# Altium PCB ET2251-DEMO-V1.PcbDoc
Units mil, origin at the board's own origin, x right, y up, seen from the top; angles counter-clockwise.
Board outline 5039.37 x 4724.41 mil, 2 copper layers (Top Layer, Bottom Layer); 99 components, 49 nets, 309 pads, 342 vias.
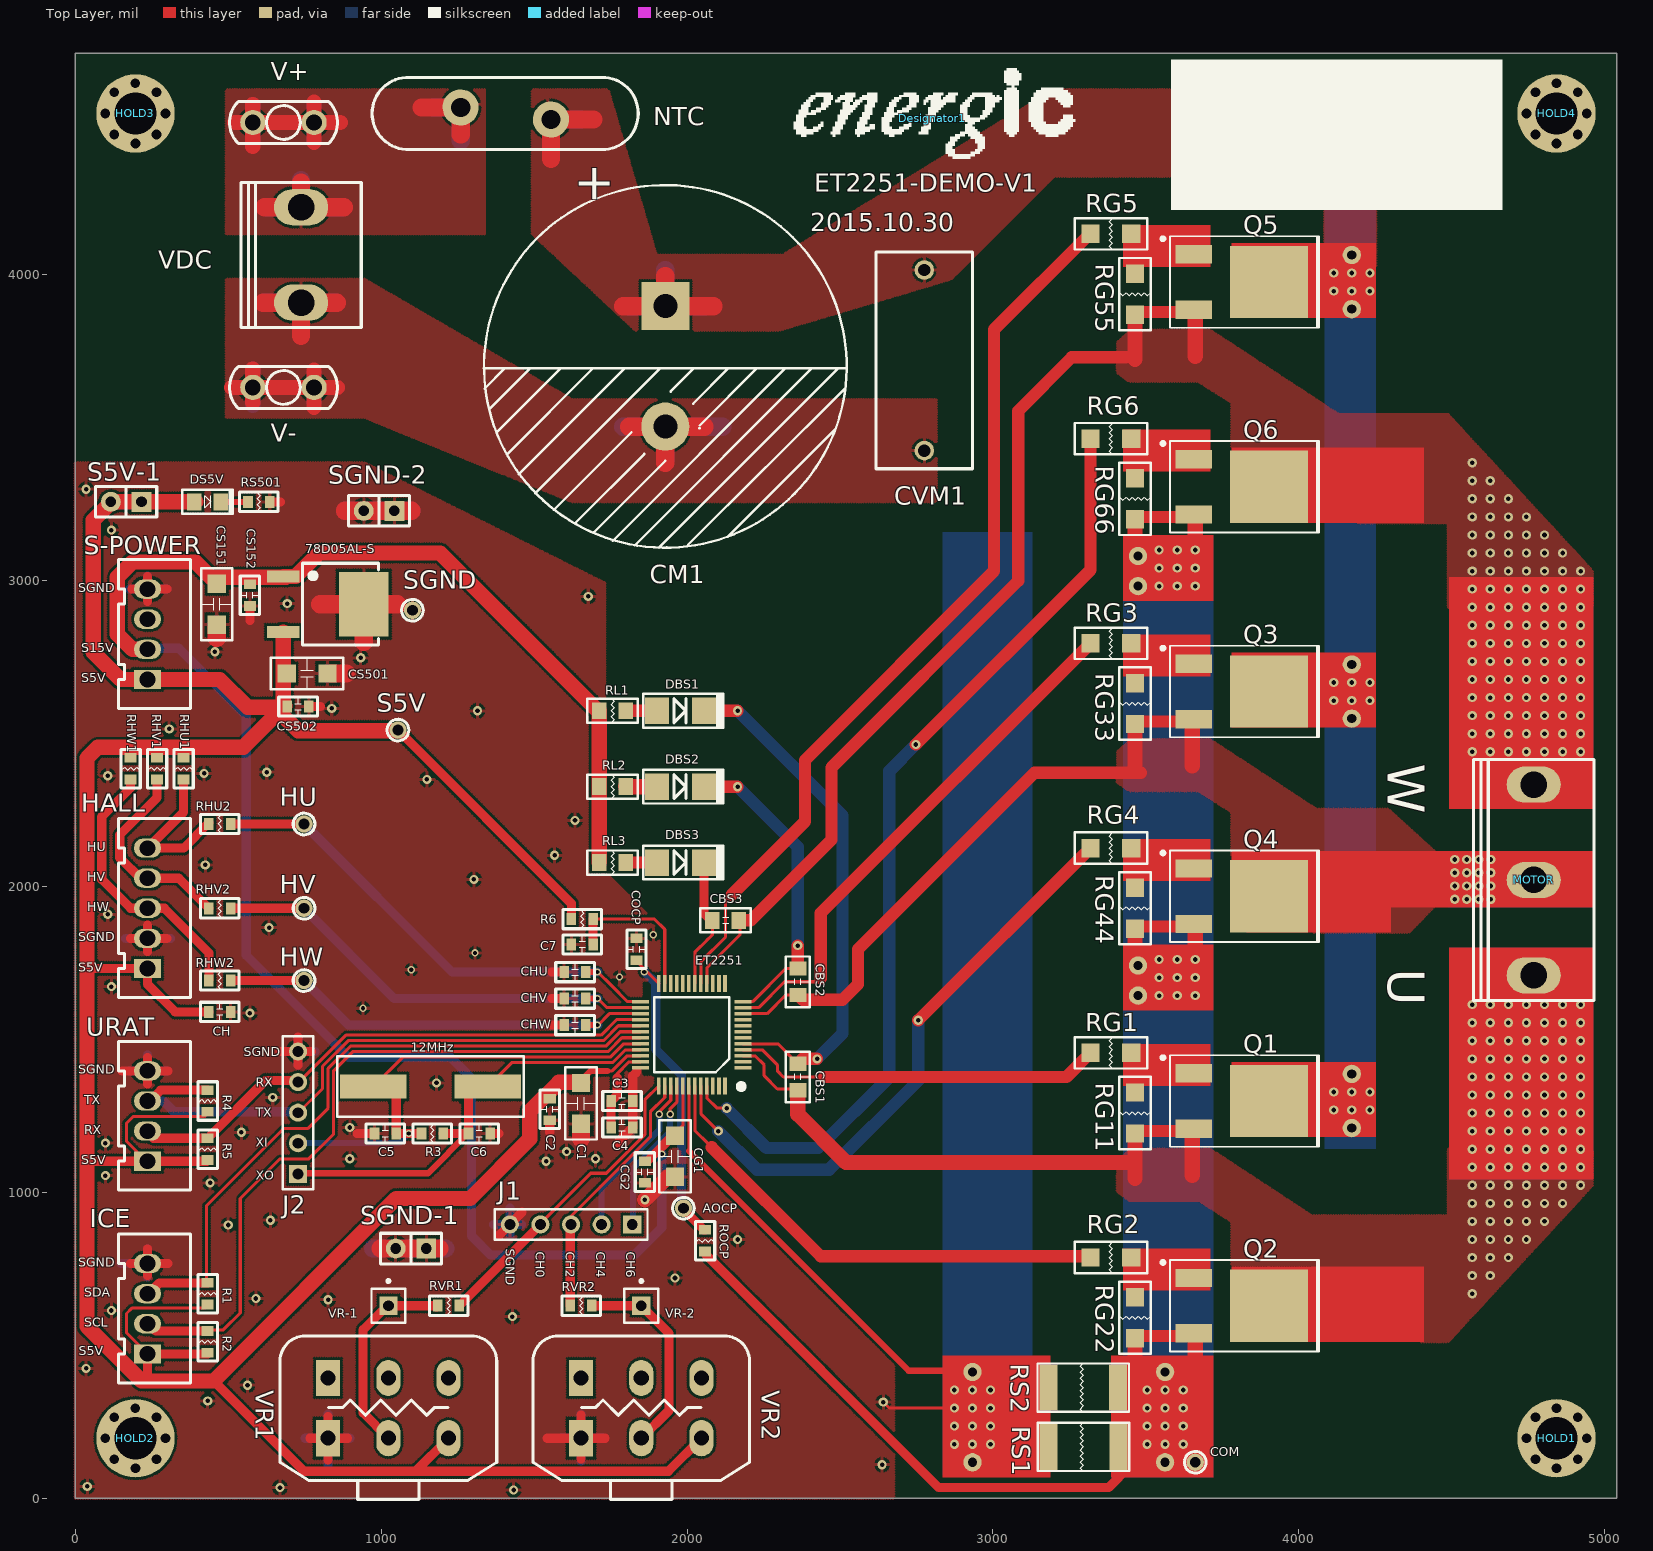
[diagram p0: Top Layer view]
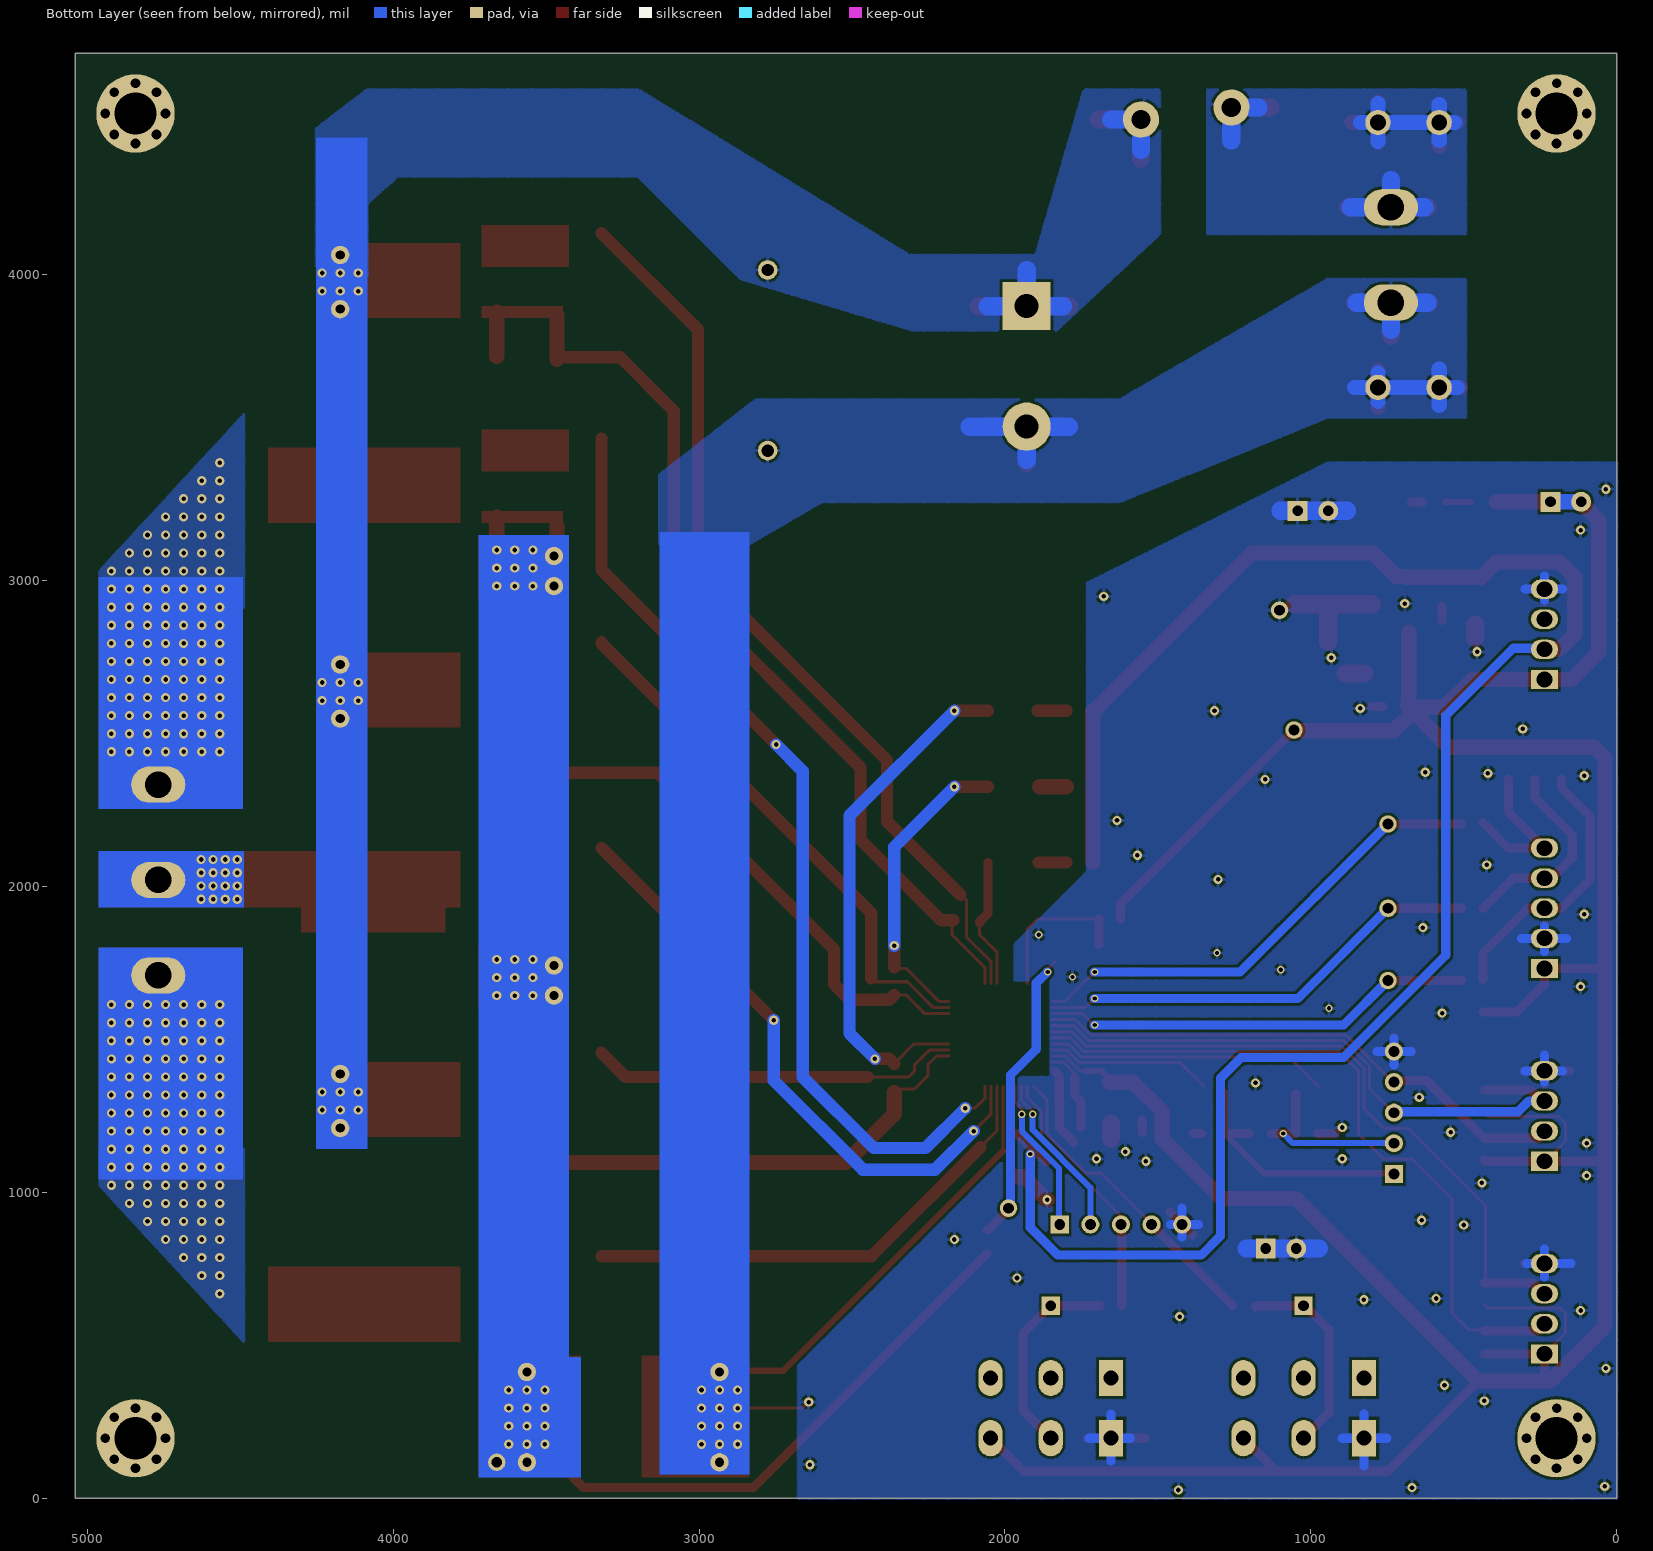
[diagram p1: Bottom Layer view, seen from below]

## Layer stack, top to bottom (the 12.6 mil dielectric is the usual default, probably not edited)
Top Solder: solder mask 0.4, Solder Resist, Dk 3.5
Top Layer: signal copper 1.4
Dielectric1: dielectric 12.6, FR-4, Dk 4.8
Bottom Layer: signal copper 1.4
Bottom Solder: solder mask 0.4, Solder Resist, Dk 3.5

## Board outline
0,0 0,4724.41 5039.37,4724.41 5039.37,0

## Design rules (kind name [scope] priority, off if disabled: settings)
Clearance [All] p1: gap=8
MinimumSolderMaskSliver [All] p1: minsoldermaskwidth=5
PolygonConnect [All] p1: connectstyle=Relief reliefconductorwidth=10 reliefentries=4 polygonreliefangle="90 Angle" airgapwidth=10
RoutingVias [All] p1: holewidth=30 width=100 viastyle="Through Hole" minholewidth=8 minwidth=8 maxholewidth=28 maxwidth=50
SilkToSilkClearance [All] p1: silktosilkclearance=5
SilkToSolderMaskClearance SilkscreenOverComponentPads [IsPad] p1: minsilkscreentomaskgap=0 clearancetoexposedcopper=TRUE
SolderMaskExpansion [All] p1: expansion=4
UnpouredPolygon [All] p1: allowunpoured=FALSE
Width [All] p1: maxlimit=250 minlimit=10 preferedwidth=10
26 further rules are at their usual default settings.

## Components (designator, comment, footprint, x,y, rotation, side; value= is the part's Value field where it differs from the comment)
12MHz "12MHz" XTAL-SMD 1348.43,1346.46 r0 top
78D05AL-S "UTC78D05AL/DPAK" IC-7805-DPAK 836.61,2923.23 r270 top
AOCP "" TP-R-0.9mm 1988.19,948.82 r90 top
C1 "10UF/25V/1206" C1206 1653.54,1291.34 r270 top
C2 "0.1UF/50V/0603" C0603 1551.18,1271.65 r90 top
C3 "1UF/16V/0603" C0603 1787.4,1299.21 r180 top
C4 "0.1UF/50V/0603" C0603 1787.4,1212.6 r180 top
C5 "22pF/25V/0603" C0603 1013.78,1192.91 r0 top
C6 "22PF/25V/0603" C0603 1320.87,1192.91 r180 top
C7 "1UF/16V/0603" C0603 1657.48,1811.02 r0 top
CBS1 "1UF/25V/0805" C0805 2362.2,1377.95 r90 top
CBS2 "1UF/25V/0805" C0805 2362.2,1688.98 r90 top
CBS3 "1UF/25V/0805" C0805 2125.98,1889.76 r180 top
CG1 "10UF/25V/1206" C1206 1960.63,1118.11 r90 top
CG2 "0.1UF/50V/0603" C0603 1862.2,1066.93 r90 top
CH "1UF/16V/0603" C0603 472.44,1590.55 r180 top
CHU "1000PF/50V/0603" C0603 1633.86,1720.47 r180 top
CHV "1000PF/50V/0603" C0603 1633.86,1633.86 r180 top
CHW "1000PF/50V/0603" C0603 1633.86,1547.24 r180 top
CM1 "470UF/400V" C-30MM-10PITCH 1929.13,3897.64 r0 top locked
COCP "1000PF/50V/0603" C0603 1834.65,1795.28 r90 top
COM "" TP-R-0.9mm 3661.42,118.11 r270 top
CS151 "10UF/25V/1206" C1206 462.6,2923.23 r270 top
CS152 "0.1UF/50V/0603" C0603 570.87,2952.76 r270 top
CS501 "10UF/25V/1206" C1206 757.87,2696.85 r0 top
CS502 "0.1UF/50V/0603" C0603 728.35,2588.58 r0 top
CVM1 "1UF/450V/DIP" C-18x7-P15 2775.59,3720.47 r270 top
DBS1 "ES1J/SMA(DO-214AC)" D-DO214AC-12 1901.58,2574.8 r180 top
DBS2 "ES1J/SMA(DO-214AC)" D-DO214AC-12 1901.57,2326.77 r180 top
DBS3 "ES1J/SMA(DO-214AC)" D-DO214AC-12 1901.57,2078.74 r180 top
Designator1 "Comment" energic 2801.18,4511.81 r0 top
DS5V "LED/0805" LED-0805 433.07,3257.87 r0 top
ET2251 "ET2251" IC-LQFP7x7-48 2015.75,1515.75 r180 top locked
HALL "" CON-5P-2.5 236.22,1732.28 r90 top
HOLD1 "TP" HOLD-3-6 4842.52,196.85 r0 top
HOLD2 "TP" HOLD-3-6 196.85,196.85 r0 top
HOLD3 "TP" HOLD-3-6 196.85,4527.56 r0 top
HOLD4 "TP" HOLD-3-6 4842.52,4527.56 r0 top
HU "" TP-R-0.9mm 748.03,2204.72 r0 top
HV "" TP-R-0.9mm 748.03,1929.13 r0 top
HW "" TP-R-0.9mm 748.03,1692.91 r0 top
ICE "CON4/2.5/180" CON-4P-2.5 236.22,472.44 r90 top
J1 "CON5/2.5/180" HDR1X5 1820.87,895.67 r180 top
J2 "CON5/2.5/180" HDR1X5 728.35,1061.02 r90 top
MOTOR "Header 5" CON-5-2P-3.96 4767.83,2021.69 r270 top
NTC "SCK15204" 11212005001 1259.84,4547.24 r180 top locked
Q1 "MOSFET/TO-252" TO-252 3779.53,1299.21 r180 top (schematic designator Q-VP)
Q2 "MOSFET/TO-252" TO-252 3779.53,629.92 r180 top (schematic designator Q-UN)
Q3 "MOSFET/TO-252" TO-252 3779.53,2637.8 r180 top (schematic designator Q-UP)
Q4 "MOSFET/TO-252" TO-252 3779.53,1968.5 r180 top (schematic designator Q-UN)
Q5 "MOSFET/TO-252" TO-252 3779.53,3976.38 r180 top (schematic designator Q-UP)
Q6 "MOSFET/TO-252" TO-252 3779.53,3307.09 r180 top (schematic designator Q-UN)
R1 "4.7K/0603" R0603 433.07,669.29 r270 top
R2 "4.7K/0603" R0603 433.07,511.81 r270 top
R3 "1M/0603" R0603 1167.32,1192.91 r0 top
R4 "4.7K/0603" R0603 433.07,1299.21 r270 top
R5 "4.7K/0603" R0603 433.07,1141.73 r270 top
R6 "10K/0603" R0603 1657.48,1893.7 r180 top
RG1 "100R/1206" R1206 3385.83,1456.69 r0 top
RG2 "100R/1206" R1206 3385.83,787.4 r0 top
RG3 "100R/1206" R1206 3385.83,2795.28 r0 top (schematic designator RG1)
RG4 "100R/1206" R1206 3385.83,2125.98 r0 top (schematic designator RG2)
RG5 "100R/1206" R1206 3385.83,4133.86 r0 top (schematic designator RG1)
RG6 "100R/1206" R1206 3385.83,3464.57 r0 top (schematic designator RG2)
RG11 "10K/1206" R1206 3464.57,1259.84 r90 top
RG22 "10K/1206" R1206 3464.57,590.55 r90 top
RG33 "10K/1206" R1206 3464.57,2598.43 r90 top (schematic designator RG11)
RG44 "10K/1206" R1206 3464.57,1929.13 r90 top (schematic designator RG22)
RG55 "10K/1206" R1206 3464.57,3937.01 r90 top (schematic designator RG11)
RG66 "10K/1206" R1206 3464.57,3267.72 r90 top (schematic designator RG22)
RHU1 "1K/0603" R0603 354.33,2385.83 r270 top
RHU2 "3.3K/0603" R0603 472.44,2204.72 r0 top
RHV1 "1K/0603" R0603 267.72,2385.83 r270 top
RHV2 "3.3K/0603" R0603 472.44,1929.13 r0 top
RHW1 "1K/0603" R0603 181.1,2385.83 r270 top
RHW2 "3.3K/0603" R0603 472.44,1692.91 r0 top
RL1 "22R/0805" R0805 1755.91,2574.8 r0 top
RL2 "22R/0805" R0805 1755.91,2326.77 r0 top
RL3 "22R/0805" R0805 1755.91,2078.74 r0 top
ROCP "2.2K/0603" R0603 2059.06,842.52 r270 top
RS1 "0.51R/2W/2512" R2512 3295.94,168.22 r180 top
RS2 "0.51R/2W/2512" R2512 3295.28,362.2 r180 top
RS501 "4.7K/0603" R0603 600.39,3257.87 r180 top
RVR1 "0R/0603" R0603 1220.47,629.92 r180 top
RVR2 "0R/0603" R0603 1653.54,629.92 r0 top
S5V "" TP-R-0.9mm 1055.12,2511.81 r0 top
S5V-1 "Header 2" CON-SIP2 216.54,3257.87 r180 top
S-POWER "CON4/2.5/180" CON-4P-2.5 236.22,2677.17 r90 top
SGND "" TP-R-0.9mm 1102.36,2903.54 r90 top
SGND-1 "Header 2" CON-SIP2 1147.64,816.93 r180 top
SGND-2 "Header 2" CON-SIP2 1043.31,3228.35 r180 top
URAT "CON4/2.5/180" CON-4P-2.5 236.22,1102.36 r90 top
V+ "(250T)" CON-P-850 580.71,4498.03 r0 top
V- "(250T)" CON-P-850 580.71,3631.89 r0 top
VDC "CON3/P3.96/180/ALEX" CON-3-1P-3.96 738.19,4064.96 r270 top
VR1 "10K/VR/DIP" VR-6P-5.0 1023.62,196.85 r180 top
VR2 "10K/VR/DIP" VR-6P-5.0 1850.39,196.85 r180 top
VR-1 "Plug" PIN1 1023.62,629.92 r0 top
VR-2 "Plug" PIN1 1850.39,629.92 r0 top

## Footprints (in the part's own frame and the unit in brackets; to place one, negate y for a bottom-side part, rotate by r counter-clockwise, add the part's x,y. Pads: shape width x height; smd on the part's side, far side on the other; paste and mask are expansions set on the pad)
11212005001 [mm]
  round 3 hole 1.6: 1(0,0) 2(-7.5,1.001)
  silkscreen extent -14.75,-2.5 7.35,3.5
C0603 [mm]
  rect 0.8x1 smd: 1(-0.9,0) 2(0.9,0)
  silkscreen extent -1.6,-0.8 1.6,0.8
C0805 [mm]
  rect 1.2x1.4 smd: 1(-1.1,0) 2(1.1,0)
  silkscreen extent -2.1,-1 2.1,1
C1206 [mil]
  rect 60x60 smd: 1(66.93,0) 2(-66.93,0)
  silkscreen extent -118,-51 118,51
C-18x7-P15 [mil]
  round 64 hole 40: 1(-295.28,0) 2(295.28,0)
  silkscreen extent -354,-157 354,157
C-30MM-10PITCH [mm]
  rect 4x4 hole 2: 1(0,0)
  round 4 hole 2: 2(0,-10)
  silkscreen extent -15.08,-20.06 15.06,10.05
CON-3-1P-3.96 [mm]
  oval 3x4.5 hole 2.2: 1(-3.96,0) 3(3.96,0)
  silkscreen extent -6.02,-5 6.02,5
CON-4P-2.5 [mm]
  rect 1.6x2.25 hole 1.3: 1(0,0)
  oval 1.6x2.25 hole 1.3: 2(2.5,0) 3(5,0) 4(7.5,0)
  silkscreen extent -2.4,-3.56 9.95,2.4
CON-5-2P-3.96 [mm]
  oval 3x4.5 hole 2.2: 1(-7.92,0) 3(0,0) 5(7.92,0)
  silkscreen extent -10,-5 10,5
CON-5P-2.5 [mm]
  rect 1.6x2.25 hole 1.3: 1(0,0)
  oval 1.6x2.25 hole 1.3: 2(2.5,0) 3(5,0) 4(7.5,0) 5(10,0)
  silkscreen extent -2.4,-3.56 12.45,2.4
CON-P-850 [mm]
  round 2.1 hole 1.3: 1(0,0) 1(5.08,0)
  silkscreen extent -1.93,-1.75 7.01,1.75
CON-SIP2 [mil]
  rect 65x65 hole 35: 1(0,0)
  round 65 hole 35: 2(100,0)
  silkscreen extent -50,-50 150,50
D-DO214AC-12 [mm]
  rect 2x2.2 smd: 1(0,0) 2(-3.9,0)
  silkscreen extent -5.5,-1.4 1.14,1.4
energic [mil]
  silkscreen extent -452,-132 468,164
HDR1X5 [mm] "Connector; Header; 5 Position"
  rect 1.5x1.5 hole 0.9: 1(0,0)
  round 1.5 hole 0.9: 2(2.54,0) 3(5.08,0) 4(7.62,0) 5(10.16,0)
  silkscreen extent -1.27,-1.27 11.43,1.27
HOLD-3-6 [mm]
  round 1.2 hole 0.8: 1(-2.5,0) 1(-1.75,-1.75) 1(-1.75,1.75) 1(-0.004,2.5) 1(0,-2.5) 1(1.75,-1.75) 1(1.75,1.75) 1(2.5,0)
  round 6.5 hole 3.5: 1(0,0)
IC-7805-DPAK [mm]
  rect 1x2.7 smd: 1(-2.3,-3.985) 3(2.3,-3.985)
  rect 5.35x4.1 smd: 2(0,2.715)
  rect 4.5x1 on Top Paste: ""(0,2.715) ""(0,3.985) ""(0,1.445)
  silkscreen extent -3.4,-2.38 3.4,3.92
IC-LQFP7x7-48 [mm]
  rect 1.4x0.3 smd: 1(-4.25,2.75) 2(-4.25,2.25) 3(-4.25,1.75) 4(-4.25,1.25) 5(-4.25,0.75) 6(-4.25,0.25) 7(-4.25,-0.25) 8(-4.25,-0.75) 9(-4.25,-1.25) 10(-4.25,-1.75) 11(-4.25,-2.25) 12(-4.25,-2.75) 25(4.25,-2.75) 26(4.25,-2.25) 27(4.25,-1.75) 28(4.25,-1.25) 29(4.25,-0.75) 30(4.25,-0.25) 31(4.25,0.25) 32(4.25,0.75) 33(4.25,1.25) 34(4.25,1.75) 35(4.25,2.25) 36(4.25,2.75)
  rect 0.3x1.4 smd: 13(-2.75,-4.25) 14(-2.25,-4.25) 15(-1.75,-4.25) 16(-1.25,-4.25) 17(-0.75,-4.25) 18(-0.25,-4.25) 19(0.25,-4.25) 20(0.75,-4.25) 21(1.25,-4.25) 22(1.75,-4.25) 23(2.25,-4.25) 24(2.75,-4.25) 37(2.75,4.25) 38(2.25,4.25) 39(1.75,4.25) 40(1.25,4.25) 41(0.75,4.25) 42(0.25,4.25) 43(-0.25,4.25) 44(-0.75,4.25) 45(-1.25,4.25) 46(-1.75,4.25) 47(-2.25,4.25) 48(-2.75,4.25)
  silkscreen extent -4.3,-3.11 3.11,4.5
LED-0805 [mm]
  rect 1.2x1.4 smd: 1(-1.1,0) 2(1.1,0)
  silkscreen extent -2.1,-1 2.1,1
PIN1 [mm] "Connector; Plug"
  rect 1.5x1.5 hole 0.9: 1(0,0)
  silkscreen extent -1.4,-1.4 1.4,2.17
R0603 [mm]
  rect 0.8x1 smd: 1(-0.9,0) 2(0.9,0)
  silkscreen extent -1.6,-0.8 1.6,0.8
R0805 [mm]
  rect 1.2x1.4 smd: 1(-1.1,0) 2(1.1,0)
  silkscreen extent -2.1,-1.01 2.1,1.05
R1206 [mil]
  rect 60x60 smd: 1(66.93,0) 2(-66.93,0)
  silkscreen extent -118,-51 118,51
R2512 [mm]
  rect 1.5x3.8 smd: 1(2.9,0) 2(-2.9,0)
  silkscreen extent -3.8,-2.03 3.8,2.03
TO-252 [mm]
  rect 6.5x6 smd: D(-3.125,0)
  rect 3.048x1.524 smd: G(3.125,-2.3) S(3.125,2.3)
  silkscreen extent -7.3,-3.8 5.81,3.8
TP-R-0.9mm [mm]
  round 1.45 hole 0.9: 1(0,0)
  silkscreen extent -0.9,-0.9 0.9,0.9
VR-6P-5.0 [mm]
  rect 2x3 hole 1.25: 1(5,0) 4(5,-5)
  oval 2x3 hole 1.25: 2(0,0) 3(-5,0) 5(0,-5) 6(-5,-5)
  silkscreen extent -9,-8.5 9,5.08
XTAL-SMD [mm]
  rect 5.5x2 smd: 1(0,0) 2(-9.5,0)
  silkscreen extent -12.5,-2.5 3,2.5

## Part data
12MHz: library part 12MHZ/H, "HC-49S,12.000000MHz,+-30ppm,JXC,SMD,¥x¿³¹q¤l"
AOCP COM HU HV HW S5V SGND: library part "TEST POINT", "TEST POINT"
C3 CH CHU CHV CHW: library part 0.1UF/50V/0603
C5 C7: library part 18PF/25V/0603
C6: library part 18PF/25V/0603, "18pF,25V,∮5%,NPO,0603"
CBS1 CBS2 CBS3: library part 1UF/25V/, "1uF(105),25V,¡Ó15%,X7R,0805,PSA(¥@·R)"
CG1: library part 10U, "´¹¤ù¹q®e 10uF(106),25V,+/-10%,X5R,1206,¥@·R"
CG2: "0.1uF(104)(100n),50V,∮10%,X7R,0603,PSA"
CM1: library part 10UF/450V/10*20
COCP: "1000pF(102)(1n),50V,∮10%,X7R,0603,PSA"
DBS1 DBS2 DBS3: library part ES1J/SMA(DO-214A, "ES1J , 600V , 1A , DO-214AC,碔方;ES1J,600V,1A,DO-214AC,Lite-On"
DS5V: library part LED-LC170JRCT/0805, "LED RED, L-C170JRCT, SMD0805"
HALL: library part CON5, "Connector"
HOLD1 HOLD2 HOLD3 HOLD4 V+ V-: library part CON1, "Connector"
ICE S-POWER URAT: library part CON4, "Header 180«×,CX-W2501-04,Pitch:2.5mm,4Pin,©Ó¬¨"
J1 J2: library part "Header 5", "Header, 5-Pin"
MOTOR: "Header, 5-Pin"
NTC RL1 RL2 RL3: library part RES1
Q1 Q2 Q3 Q4 Q5 Q6: library part IRFR420, "N-Channel MOSFET"
R1 R2 R4 R5 RG1 RG2 RG3 RG4 RG5 RG6 RG11 RG22 RG33 RG44 RG55 RG66: library part 5.1K/0603
R6: "10K,1%,0603,PSA"
RHU1 RHU2 RHV1 RHV2 RHW1 RHW2: library part 330R/0603
ROCP RVR1 RVR2: library part 100R/0, "100R,1%,0603,PSA,¥@·R"
RS1 RS2: "0.51R,1%,2W,2512"
S5V-1 SGND-1 SGND-2: "Header, 2-Pin"
VDC: "8673(180«×),3Pin,Pitch:3.96,L:11.88mm*W:10.3mm*H:17.45mm,ALEX"
VR1 VR2: library part 10K/336, "3362W,10K(103),∮10%,ミΑ,DIP"

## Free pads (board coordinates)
  round 60 hole 30: 107(2933.07,118.11) 107(2933.07,413.39) 107(3474.41,1643.7) 107(3474.41,1742.13) 107(3474.41,2982.28) 107(3474.41,3080.71) 107(3562.99,118.11) 107(3562.99,413.39) 107(4173.23,1210.63) 107(4173.23,1387.8) 107(4173.23,2549.21) 107(4173.23,2726.38) 107(4173.23,3887.8) 107(4173.23,4064.96)

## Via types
v1: diameter 30, hole 15, Top Layer to Bottom Layer, 329 vias
v2: diameter 23.62, hole 13.78, Top Layer to Bottom Layer, 13 vias

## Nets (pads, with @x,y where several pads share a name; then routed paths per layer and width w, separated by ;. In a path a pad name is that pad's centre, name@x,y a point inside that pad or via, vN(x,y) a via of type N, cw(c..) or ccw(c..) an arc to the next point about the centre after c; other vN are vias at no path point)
CH0: ET2251.37 J1.4 RVR1.1 | length 1016.7
  Top Layer w10: J1.4@1519.68,897.64 1685.04,1062.99 1736.22,1062.99 1862.2,1188.98 1862.2,1303.15 ET2251.37
  Top Layer w30: RVR1.1 1515.75,889.76 J1.4@1515.75,897.64
CH2: ET2251.38 J1.3 RVR2.1 | length 841.7
  Top Layer w10: J1.3 1620.87,922.18 1880.2,1181.52 1880.2,1263.78 1927.17,1310.74 ET2251.38 ; J1.3@1622.05,893.7 J1.3@1622.44,894.09
  Top Layer w30: RVR2.1 1618.11,885.83 J1.3@1622.05,889.76
CH4: ET2251.39 J1.2 | length 548.5
  Top Layer w10: v2(1909.45,1255.91) 1909.45,1263.78 1946.85,1301.18 ET2251.39
  Bottom Layer w20: J1.2@1720.47,893.7 1720.47,1015.75 1909.45,1204.72 v2(1909.45,1255.91)
CH6: ET2251.40 J1.1 | length 510.3
  Top Layer w10: v2(1944.88,1255.91) 1944.88,1273.76 1966.54,1295.41 ET2251.40
  Bottom Layer w20: J1.1@1822.83,897.64 1822.83,1078.51 1944.88,1200.56 v2(1944.88,1255.91)
COM: COM.1 pad.107@3474.41,1643.7 pad.107@3474.41,1742.13 pad.107@3474.41,2982.28 pad.107@3474.41,3080.71 pad.107@3562.99,118.11 pad.107@3562.99,413.39 Q2.S Q4.S Q6.S RG22.2 RG44.2 RG66.2 ROCP.2 RS1.2 RS2.2 | length 2600.1
  Top Layer w30: ROCP.2@2059.06,799.21 2822.83,35.43 3377.95,35.43 3448.82,106.3
  Top Layer w50: 3464.57,357.87 RG22.2@3464.57,501.97 ; 3464.57,1696.46 RG44.2@3464.57,1840.55 ; 3464.57,3035.04 RG66.2@3464.57,3179.13 ; 3661.42,387.4 Q2.S@3661.42,531.5 ; 3661.42,1725.98 Q4.S@3661.42,1870.08 ; 3661.42,3064.57 Q6.S@3661.42,3208.66
  other v1: 3503.94,177.17 3562.99,177.17 3622.05,177.17 3503.94,236.22 3562.99,236.22 3622.05,236.22 3503.94,295.28 3562.99,295.28 3622.05,295.28 3503.94,354.33 3562.99,354.33 3622.05,354.33 3543.31,1643.7 3602.36,1643.7 3661.42,1643.7 3543.31,1702.76 3602.36,1702.76 3661.42,1702.76 3543.31,1761.81 3602.36,1761.81 3661.42,1761.81 3543.31,2982.28 3602.36,2982.28 3661.42,2982.28 3543.31,3041.34 3602.36,3041.34 3661.42,3041.34 3543.31,3100.39 3602.36,3100.39 3661.42,3100.39
HUP: CHU.1 ET2251.25 HU.1 RHU2.2 | length 1616.5
  Top Layer w10: v2@1708.66,1720.47 1751.97,1677.17 1805.12,1624.02 ET2251.25
  Top Layer w20: CHU.1 v2@1704.72,1720.47
  Top Layer w30: RHU2.2 HU.1
  Bottom Layer w30: HU.1 1232.28,1720.47 v2(1706.69,1720.47) v2@1708.66,1720.47
HVP: CHV.1 ET2251.26 HV.1 RHV2.2 | length 1504.6
  Top Layer w10: v2@1708.66,1633.86 1738.19,1604.33 ET2251.26
  Top Layer w20: CHV.1 v2(1706.69,1633.86)
  Top Layer w30: RHV2.2 HV.1@740.16,1929.13
  Bottom Layer w30: HV.1 1043.31,1633.86 v2@1708.66,1633.86
HWP: CHW.1 ET2251.27 HW.1 RHW2.2 | length 1451.8
  Top Layer w10: v2@1708.66,1547.24 1746.06,1584.65 ET2251.27
  Top Layer w20: CHW.1 v2@1704.72,1547.24
  Top Layer w30: RHW2.2 HW.1
  Bottom Layer w30: HW.1 893.7,1547.24 v2(1706.69,1547.24) v2@1708.66,1547.24
MU: CBS1.1 ET2251.3 MOTOR.5 Q1.S Q2.D RG11.2 | length 1771.4
  Top Layer w10: ET2251.3 2222.44,1446.85 2251.97,1417.32 2251.97,1381.89 2295.28,1338.58 CBS1.1@2362.2,1338.58
  Top Layer w50: CBS1.1@2362.2,1326.77 2362.2,1255.91 2519.68,1098.43 3464.57,1098.43 ; 3464.57,1046.85 RG11.2@3464.57,1190.94 ; 3651.57,1056.69 Q1.S@3651.57,1200.79
  other v1: 4566.93,669.29 4566.93,728.35 4625.98,728.35 4566.93,787.4 4625.98,787.4 4685.04,787.4 4566.93,846.46 4625.98,846.46 4685.04,846.46 4744.09,846.46 4566.93,905.51 4625.98,905.51 4685.04,905.51 4744.09,905.51 4803.15,905.51 4566.93,964.57 4625.98,964.57 4685.04,964.57 4744.09,964.57 4803.15,964.57 4862.2,964.57 4566.93,1023.62 4625.98,1023.62 4685.04,1023.62 4744.09,1023.62 4803.15,1023.62 4862.2,1023.62 4921.26,1023.62 4566.93,1082.68 4625.98,1082.68 4685.04,1082.68 4744.09,1082.68 4803.15,1082.68 4862.2,1082.68 4921.26,1082.68 4566.93,1141.73 4625.98,1141.73 4685.04,1141.73 4744.09,1141.73 4803.15,1141.73 4862.2,1141.73 4921.26,1141.73 4566.93,1200.79 4625.98,1200.79 4685.04,1200.79 4744.09,1200.79 4803.15,1200.79 4862.2,1200.79 4921.26,1200.79 4566.93,1259.84 4625.98,1259.84 4685.04,1259.84 4744.09,1259.84 4803.15,1259.84 4862.2,1259.84 4921.26,1259.84 4566.93,1318.9 4625.98,1318.9 4685.04,1318.9 4744.09,1318.9 4803.15,1318.9 4862.2,1318.9 4921.26,1318.9 4566.93,1377.95 4625.98,1377.95 4685.04,1377.95 4744.09,1377.95 4803.15,1377.95 4862.2,1377.95 4921.26,1377.95 4566.93,1437.01 4625.98,1437.01 4685.04,1437.01 4744.09,1437.01 4803.15,1437.01 4862.2,1437.01 4921.26,1437.01 4566.93,1496.06 4625.98,1496.06 4685.04,1496.06 4744.09,1496.06 4803.15,1496.06 4862.2,1496.06 4921.26,1496.06 4566.93,1555.12 4625.98,1555.12 4685.04,1555.12 4744.09,1555.12 4803.15,1555.12 4862.2,1555.12 4921.26,1555.12 4566.93,1614.17 4625.98,1614.17 4685.04,1614.17 4744.09,1614.17 4803.15,1614.17 4862.2,1614.17 4921.26,1614.17
MV: CBS2.1 ET2251.10 MOTOR.3 Q3.S Q4.D RG33.2 | length 1998.8
  Top Layer w10: ET2251.10 2261.81,1584.65 2322.83,1645.67 CBS2.1 CBS2.1@2366.14,1645.67
  Top Layer w40: CBS2.1 2377.95,1629.92 2507.87,1629.92 2559.06,1681.1 2559.06,1795.28 3135.83,2372.05 3483.66,2372.05
  Top Layer w50: 3464.57,2385.43 RG33.2@3464.57,2529.53 ; 3651.57,2395.28 Q3.S@3651.57,2539.37
  other v1: 4509.84,1958.66 4549.21,1958.66 4588.58,1958.66 4627.95,1958.66 4509.84,2001.97 4549.21,2001.97 4588.58,2001.97 4627.95,2001.97 4509.84,2045.28 4549.21,2045.28 4588.58,2045.28 4627.95,2045.28 4509.84,2088.58 4549.21,2088.58 4588.58,2088.58 4627.95,2088.58
MW: CBS3.1 ET2251.16 MOTOR.1 Q5.S Q6.D RG55.2 | length 3027.5
  Top Layer w10: ET2251.16 2064.96,1734.25 2114.17,1783.46 2173.23,1842.52 CBS3.1@2173.23,1885.83
  Top Layer w40: CBS3.1 2208.66,1889.76 2472.44,2153.54 2472.44,2389.76 3082.68,3000 3082.68,3555.12 3257.87,3730.32 3435.04,3730.32
  Top Layer w50: 3464.57,3724.02 RG55.2@3464.57,3868.11 ; 3661.42,3733.86 Q5.S@3661.42,3877.95
  other v1: 4566.93,2440.95 4625.98,2440.95 4685.04,2440.95 4744.09,2440.95 4803.15,2440.95 4862.2,2440.95 4921.26,2440.95 4566.93,2500 4625.98,2500 4685.04,2500 4744.09,2500 4803.15,2500 4862.2,2500 4921.26,2500 4566.93,2559.06 4625.98,2559.06 4685.04,2559.06 4744.09,2559.06 4803.15,2559.06 4862.2,2559.06 4921.26,2559.06 4566.93,2618.11 4625.98,2618.11 4685.04,2618.11 4744.09,2618.11 4803.15,2618.11 4862.2,2618.11 4921.26,2618.11 4566.93,2677.17 4625.98,2677.17 4685.04,2677.17 4744.09,2677.17 4803.15,2677.17 4862.2,2677.17 4921.26,2677.17 4566.93,2736.22 4625.98,2736.22 4685.04,2736.22 4744.09,2736.22 4803.15,2736.22 4862.2,2736.22 4921.26,2736.22 4566.93,2795.28 4625.98,2795.28 4685.04,2795.28 4744.09,2795.28 4803.15,2795.28 4862.2,2795.28 4921.26,2795.28 4566.93,2854.33 4625.98,2854.33 4685.04,2854.33 4744.09,2854.33 4803.15,2854.33 4862.2,2854.33 4921.26,2854.33 4566.93,2913.39 4625.98,2913.39 4685.04,2913.39 4744.09,2913.39 4803.15,2913.39 4862.2,2913.39 4921.26,2913.39 4566.93,2972.44 4625.98,2972.44 4685.04,2972.44 4744.09,2972.44 4803.15,2972.44 4862.2,2972.44 4921.26,2972.44 4566.93,3031.5 4625.98,3031.5 4685.04,3031.5 4744.09,3031.5 4803.15,3031.5 4862.2,3031.5 4921.26,3031.5 4566.93,3090.55 4625.98,3090.55 4685.04,3090.55 4744.09,3090.55 4803.15,3090.55 4862.2,3090.55 4566.93,3149.61 4625.98,3149.61 4685.04,3149.61 4744.09,3149.61 4803.15,3149.61 4566.93,3208.66 4625.98,3208.66 4685.04,3208.66 4744.09,3208.66 4566.93,3267.72 4625.98,3267.72 4685.04,3267.72 4566.93,3326.77 4625.98,3326.77 4566.93,3385.83
NetAOCP_1: AOCP.1 COCP.1 ET2251.24 ROCP.1 | length 1031
  Top Layer w10: COCP.1@1834.65,1755.91 ET2251.24
  Top Layer w30: AOCP.1@1984.25,948.82 2055.12,877.95 ROCP.1
  Bottom Layer w30: v2@1862.2,1720.47 1897.64,1685.04 1897.64,1468.5 1981.69,1384.46 1981.69,955.32 AOCP.1
  other v2: 1860.24,1720.47
NetDBS1_1: DBS1.1 RL1.2 | length 94.5
  Top Layer w40: RL1.2 DBS1.1@1893.7,2574.8
NetDBS2_1: DBS2.1 RL2.2 | length 86.6
  Top Layer w50: RL2.2 DBS2.1@1885.83,2326.77
NetDBS3_1: DBS3.1 RL3.2 | length 90.6
  Top Layer w40: RL3.2 DBS3.1@1889.76,2078.74
NetDS5V_2: DS5V.2 RS501.2 | length 84.6
  Top Layer w20: DS5V.2 RS501.2@561.02,3257.87
NetHALL_3: HALL.3 RHW1.2 RHW2.1 | length 902.4
  Top Layer w30: RHW1.2 181.1,2322.83 86.61,2228.35 86.61,2023.62 181.1,1929.13 HALL.3 291.34,1929.13 437.01,1783.46 RHW2.1@437.01,1696.85
NetHALL_4: HALL.4 RHV1.2 RHV2.1 | length 667.9
  Top Layer w30: HALL.4@236.22,2023.62 216.54,2023.62 145.67,2094.49 145.67,2169.29 267.72,2291.34 RHV1.2 ; HALL.4 338.58,2027.56 RHV2.1
NetHALL_5: HALL.5 RHU1.2 RHU2.1 | length 508.4
  Top Layer w30: RHU1.2 354.33,2244.09 HALL.5 354.33,2125.98 RHU2.1@437.01,2208.66
NetNTC_1: NTC.1 V+.1 VDC.1 | length 2340.4
  Top Layer w10: 1249.46,4448.82 NTC.1@1249.46,4546.7
  Top Layer w50: 521.65,4498.03 V+.1@580.71,4498.03 ; 580.71,4419.29 V+.1@580.71,4498.03 ; 580.71,4557.09 V+.1@580.71,4498.03 ; 780.71,4432.28 V+.1@780.71,4498.03 ; 780.71,4563.78 V+.1@780.71,4498.03 ; 866.14,4498.03 V+.1@780.71,4498.03 ; V+.1@580.71,4498.03 V+.1@780.71,4498.03
  Top Layer w60: 618.5,4220.87 VDC.1 ; 738.19,4301.18 VDC.1 ; 877.56,4220.87 VDC.1 ; 1131.89,4547.24 NTC.1 1259.84,4458.66
  Bottom Layer w50: 531.5,4498.03 V+.1@580.71,4498.03 ; 580.71,4438.98 V+.1@580.71,4498.03 ; 580.71,4557.09 V+.1@580.71,4498.03 ; 780.71,4435.83 V+.1@780.71,4498.03 ; 780.71,4560.24 V+.1@780.71,4498.03 ; 836.61,4498.03 V+.1@780.71,4498.03 ; V+.1@580.71,4498.03 V+.1@780.71,4498.03
  Bottom Layer w60: 629.53,4220.87 VDC.1 ; 738.19,4309.05 VDC.1 ; 869.69,4220.87 VDC.1 ; 1171.26,4547.24 NTC.1 1259.84,4438.98
NetQ1_G: Q1.G RG1.1 RG11.1
NetQ2_G: Q2.G RG2.1 RG22.1
NetQ3_G: Q3.G RG3.1 RG33.1
NetQ4_G: Q4.G RG4.1 RG44.1
NetQ5_G: Q5.G RG5.1 RG55.1
NetQ6_G: Q6.G RG6.1 RG66.1
PGND: 78D05AL-S.2 C1.1 C2.1 C3.1 C4.1 C5.1 C6.1 C7.1 CG1.2 CG2.1 CH.1 CHU.2 CHV.2 CHW.2 CM1.2 COCP.2 CS151.1 CS152.2 CS501.1 CS502.2 CVM1.2 ET2251.36 ET2251.42 HALL.2 ICE.4 J1.5 J2.5 pad.107@2933.07,118.11 pad.107@2933.07,413.39 RS1.1 RS2.1 RS501.1 S-POWER.4 SGND-1.1 SGND-1.2 SGND-2.1 SGND-2.2 SGND.1 URAT.4 V-.1 VDC.3 VR1.1 VR2.1 | length 10000.8
  Top Layer w10: 1834.65,1393.7 ET2251.36 ; 2005.91,1135.83 ET2251.42 ; v1(2641.73,314.96) 2661.42,295.28 v1(2874.02,295.28)
  Top Layer w20: 2005.91,1135.83 2724.41,417.32 pad.107@2909.45,417.32
  Top Layer w30: 153.54,1397.64 URAT.4 ; 181.1,767.72 ICE.4 ; 181.1,1830.71 HALL.2 ; 185.8,2972.44 S-POWER.4 ; 236.22,728.35 ICE.4 ; 236.22,814.96 ICE.4 ; 236.22,1354.33 URAT.4 ; 236.22,1440.94 URAT.4 ; 236.22,1787.4 HALL.2 ; 236.22,1874.02 HALL.2 ; 236.22,2933.07 S-POWER.4 ; 236.22,3013.02 S-POWER.4 ; 299.21,1830.71 HALL.2 ; 299.21,2972.44 S-POWER.4 ; 303.15,767.72 ICE.4 ; 303.15,1397.64 URAT.4 ; 570.87,2870.08 CS152.2 ; RS501.1 671.26,3257.87 ; 668.9,1461.02 J2.5 ; 728.35,1417.32 J2.5 ; 728.35,1507.87 J2.5 ; CS502.2 801.18,2588.58 ; 767.72,196.85 VR1.1 ; 772.05,1461.02 J2.5 ; 826.77,126.58 VR1.1 ; 826.77,267.72 VR1.1 ; 889.76,196.85 VR1.1 ; 921.26,1192.91 C5.1 ; C6.1 1385.83,1192.91 ; 1387.4,862.2 J1.5 1460.63,935.43 ; 1543.31,196.85 VR2.1 ; 1547.24,1547.24 CHW.2 ; 1551.18,1196.85 C2.1 ; 1559.06,1633.86 CHV.2 ; 1559.06,1720.47 CHU.2 ; 1653.54,129.92 VR2.1 ; 1653.54,271.65 VR2.1 ; 1732.28,196.85 VR2.1 ; 1775.59,1161.42 1775.59,1165.35 C4.1 C3.1 1822.83,1381.89 1834.65,1393.7
  Top Layer w50: 511.81,3631.89 V-.1@580.71,3631.89 ; 580.71,3582.68 V-.1@580.71,3631.89 ; 580.71,3690.94 V-.1@580.71,3631.89 ; 780.71,3566.14 V-.1@780.71,3631.89 ; 780.71,3687.79 V-.1@780.71,3631.89 ; 856.3,3631.89 V-.1@780.71,3631.89 ; v1(1862.2,976.38) 1937.01,1051.18 CG1.2 ; V-.1@580.71,3631.89 V-.1@780.71,3631.89
  Top Layer w60: 462.6,2812.99 CS151.1 ; 614.57,3909.05 VDC.3 ; 738.19,3801.18 VDC.3 ; 801.18,2923.23 78D05AL-S.2 ; CS501.1 885.83,2696.85 ; 854.72,3909.05 VDC.3 ; 881.89,3228.35 SGND-2.2 SGND-2.1 1098.43,3228.35 ; 943.5,2800.59 78D05AL-S.2 ; 998.03,816.93 SGND-1.2 SGND-1.1 1190.95,816.93 ; 1053.15,2923.23 78D05AL-S.2 ; 1653.54,1177.17 C1.1 ; 1811.02,3503.94 CM1.2 ; 1929.13,3385.83 CM1.2 ; 2057.09,3503.94 CM1.2
  Bottom Layer w30: 149.61,767.72 ICE.4 ; 165.35,1830.71 HALL.2 ; 177.17,1397.64 URAT.4 ; 177.17,2972.44 S-POWER.4 ; 236.22,724.41 ICE.4 ; 236.22,814.96 ICE.4 ; 236.22,1362.2 URAT.4 ; 236.22,1448.82 URAT.4 ; 236.22,1787.4 HALL.2 ; 236.22,1870.08 HALL.2 ; 236.22,2937.01 S-POWER.4 ; 236.22,3015.75 S-POWER.4 ; 295.28,767.72 ICE.4 ; 299.21,1397.64 URAT.4 ; 299.21,2972.44 S-POWER.4 ; 311.02,1830.71 HALL.2 ; 672.83,1461.02 J2.5 ; 728.35,1417.32 J2.5 ; 728.35,1503.94 J2.5 ; 751.97,196.85 VR1.1 ; 783.07,1461.02 J2.5 ; 826.77,106.3 VR1.1 ; 826.77,275.59 VR1.1 ; 897.64,196.85 VR1.1 ; 1368.11,895.67 J1.5 ; 1420.87,854.72 J1.5 ; 1420.87,949.21 J1.5 ; 1458.66,895.67 J1.5 ; 1590.55,196.85 VR2.1 ; 1653.54,122.05 VR2.1 ; 1653.54,275.59 VR2.1 ; 1724.41,196.85 VR2.1
  Bottom Layer w50: 521.65,3631.89 V-.1@580.71,3631.89 ; 580.71,3572.83 V-.1@580.71,3631.89 ; 580.71,3690.94 V-.1@580.71,3631.89 ; 780.71,3585.83 V-.1@780.71,3631.89 ; 780.71,3677.95 V-.1@780.71,3631.89 ; 856.3,3631.89 V-.1@780.71,3631.89 ; V-.1@580.71,3631.89 V-.1@780.71,3631.89
  Bottom Layer w60: 618.5,3909.05 VDC.3 ; 738.19,3820.87 VDC.3 ; 850,3909.05 VDC.3 ; 881.89,3228.35 SGND-2.2 SGND-2.1 1098.43,3228.35 ; 974.41,816.93 SGND-1.2 SGND-1.1 1210.63,816.93 ; 1791.34,3503.94 CM1.2 ; 1929.13,3395.67 CM1.2 ; 2116.14,3503.94 CM1.2
  other v1: 1433.07,27.56 669.29,35.43 39.37,39.37 2637.8,110.24 2874.02,177.17 2933.07,177.17 2992.13,177.17 2874.02,236.22 2933.07,236.22 2992.13,236.22 2933.07,295.28 2992.13,295.28 433.07,318.9 2874.02,354.33 2933.07,354.33 2992.13,354.33 562.99,370.08 35.43,425.2 1429.13,594.49 118.11,614.17 826.77,649.61 590.55,653.54 1960.63,720.47 2165.35,846.46 500,893.7 637.8,909.45 440.94,1031.5 98.43,1055.12 1539.37,1102.36 897.64,1110.24 1700.79,1110.24 1606.3,1133.86 98.43,1161.42 543.31,1196.85 897.64,1212.6 645.67,1311.02 1181.1,1358.27 570.87,1586.61 118.11,1673.23 633.86,1866.14 106.3,1909.45 1303.15,2023.62 425.2,2070.87 1566.93,2102.36 1633.86,2216.54 1149.61,2350.39 106.3,2362.2 421.26,2370.08 625.98,2374.02 307.09,2515.75 1314.96,2574.8 838.58,2582.68 933.07,2748.03 456.69,2767.72 692.91,2925.2 1677.17,2948.82 118.11,3165.35 35.43,3299.21
  other v2: 940.94,1602.36 1779.53,1704.72 1098.43,1728.35 1307.09,1783.46 1889.76,1842.52
RSTN: C7.2 ET2251.23 R6.1 | length 506.8
  Top Layer w10: R6.1@1696.85,1893.7 1893.7,1893.7 1927.17,1860.24 ET2251.23 ; R6.1@1700.79,1889.76 R6.1@1702.76,1891.73
  Top Layer w30: C7.2 R6.1
RX: ET2251.28 J2.4 R5.1 URAT.2 | length 1778.7
  Top Layer w10: J2.4@732.28,1362.2 884.64,1514.56 1719.28,1514.56 1769.68,1564.96 ET2251.28
  Top Layer w30: URAT.2@236.22,1196.85 255.91,1177.17 R5.1 622.05,1366.14 J2.4@728.35,1366.14
S15V: 78D05AL-S.1 CG1.1 CG2.2 CS151.2 CS152.1 ET2251.41 RL1.1 RL2.1 RL3.1 S-POWER.2 | length 6517.9
  Top Layer w10: CG1.1@1964.57,1196.85 1986.22,1218.5 ET2251.41
  Top Layer w30: RL3.1@1712.6,2076.77 RL3.1 ; CG2.2 1870.08,1102.36 CG1.1@1960.63,1192.91
  Top Layer w50: S-POWER.2 187.01,2775.59 137.8,2824.8 137.8,3011.81 187.01,3061.02 393.7,3061.02 442.91,3011.81 78D05AL-S.1@688.98,3011.81 ; 78D05AL-S.1 720.47,3013.78 797.24,3090.55 1192.91,3090.55 RL1.1@1712.6,2570.87 ; RL3.1 RL1.1
  Bottom Layer w30: S-POWER.2@232.28,2779.53 338.58,2779.53 559.06,2559.06 559.06,1775.59 893.7,1440.94 1228.35,1440.94 1295.28,1374.02 1295.28,858.27 1358.27,795.28 1826.77,795.28 1917.32,885.83 v2(1917.32,1125.98)
SCL-ICE: ET2251.31 ICE.2 R2.1 | length 2356.2
  Top Layer w10: R2.1@425.2,551.18 484.25,551.18 539.37,606.3 539.37,980.32 669.29,1110.24 763.78,1110.24 844.77,1191.23 844.77,1398.33 907.01,1460.56 1741.65,1460.56 1787,1505.91 ET2251.31
  Top Layer w30: ICE.2@244.09,566.93 263.78,547.24 R2.1
SDA-ICE: ET2251.30 ICE.3 R1.1 | length 2192.4
  Top Layer w10: R1.1@429.13,708.66 429.13,956.69 681.1,1208.66 759.84,1208.66 826.77,1275.59 826.77,1405.78 899.55,1478.56 1734.2,1478.56 1781.23,1525.59 ET2251.30
  Top Layer w30: ICE.3@236.22,665.35 275.59,704.72 R1.1
TX: ET2251.29 J2.3 R4.1 URAT.3 | length 1997.1
  Top Layer w10: J2.3@728.35,1259.84 808,1339.5 808,1412.47 892.09,1496.56 1726.74,1496.56 1775.46,1545.28 ET2251.29
  Top Layer w30: URAT.3@240.16,1295.28 279.53,1334.65 R4.1
  Bottom Layer w30: URAT.3 287.4,1299.21 322.83,1263.78 J2.3@728.35,1263.78
UN: ET2251.43 RG2.2 | length 1595.5
  Top Layer w10: ET2251.43 2025.59,1202.76 2070.87,1157.48
  Top Layer w40: 2080.71,1147.64 2437.01,791.34 RG2.2@3318.9,791.34
UP: ET2251.4 RG1.2 | length 1212.7
  Top Layer w10: ET2251.4 2246.06,1466.54 2295.28,1417.32 2295.28,1397.64 2314.96,1377.95 2444.88,1377.95
  Top Layer w40: 2448.82,1377.95 3240.16,1377.95 RG1.2
V25: C3.2 C4.2 ET2251.35 | length 277
  Top Layer w10: 1771.65,1374.02 1771.65,1388.74 1810.08,1427.17 ET2251.35
  Top Layer w30: C4.2 C3.2 1771.65,1318.9 1771.65,1374.02
VB1: CBS1.2 DBS1.2 ET2251.5 | length 1730.3
  Top Layer w10: ET2251.5 2297.24,1486.22 CBS1.2 ; 2336.61,1446.85 CBS1.2@2358.27,1425.2
  Top Layer w40: DBS1.2 v1(2165.35,2574.8) ; CBS1.2 2377.95,1437.01 v1(2425.2,1437.01)
  Bottom Layer w40: v1(2165.35,2574.8) 2507.87,2232.28 2507.87,1519.68 v1(2425.2,1437.01)
VB2: CBS2.2 DBS2.2 ET2251.12 | length 1002.4
  Top Layer w10: ET2251.12 2214.57,1624.02 2322.83,1732.28 CBS2.2@2358.27,1732.28
  Top Layer w40: DBS2.2 v1(2165.35,2326.77) ; CBS2.2@2362.2,1736.22 v1(2362.2,1807.09)
  Bottom Layer w40: v1(2165.35,2326.77) 2362.2,2129.92 v1(2362.2,1807.09)
VB3: CBS3.2 DBS3.2 ET2251.18 | length 433.5
  Top Layer w10: ET2251.18 2025.59,1785.43 2066.93,1826.77 ; 2064.96,1824.8 2078.74,1838.58 2082.68,1842.52 CBS3.2@2082.68,1881.89
  Top Layer w30: DBS3.2 2055.12,1913.39 2082.68,1885.83 CBS3.2@2082.68,1881.89
VDD5: 78D05AL-S.3 C1.2 C2.2 CH.2 CS501.2 CS502.1 DS5V.1 ET2251.34 HALL.1 ICE.1 R1.2 R2.2 R4.2 R5.2 R6.2 RHU1.1 RHV1.1 RHW1.1 S5V-1.1 S5V-1.2 S5V.1 S-POWER.1 URAT.1 VR1.3 VR2.3 | length 11975.5
  Top Layer w10: URAT.1@232.28,1102.36 167.32,1167.32 167.32,1226.38 188.98,1248.03 421.26,1248.03 R4.2@433.07,1259.84 ; ICE.1 167.32,541.34 167.32,604.33 185.04,622.05 421.26,622.05 R1.2 ; 1740.16,1397.64 1755.1,1397.64 1804.31,1446.85 ET2251.34
  Top Layer w20: C1.2@1649.61,1362.2 1685.04,1397.64 1740.16,1397.64
  Top Layer w30: 39.37,1102.36 232.28,1102.36 URAT.1 429.13,1102.36 R5.2 ; 39.37,1732.28 HALL.1 236.22,1681.1 326.77,1590.55 CH.2 ; 236.22,403.54 ICE.1 R2.2@433.07,472.44 ; 452.76,383.86 748.03,88.58 1112.2,88.58 ; S5V.1 1057.09,2509.84 1622.05,1944.88 R6.2 ; VR1.3 1112.2,88.58 ; VR2.3 1938.98,88.58 1112.2,88.58
  Top Layer w50: DS5V.1@393.7,3257.87 S5V-1.1 118.11,3257.87 59.06,3198.82 59.06,2765.75 147.64,2677.17 S-POWER.1 472.44,2677.17 562.99,2586.61 CS502.1@679.72,2586.61 ; 679.72,2558.46 728.35,2509.84 S5V.1@1057.09,2509.84 ; 78D05AL-S.3 CS502.1@679.72,2586.61 ; CS502.1@685.04,2590.55 CS502.1@681.1,2586.61 ; C1.2@1659.45,1360.24 1580.71,1360.24 1485.76,1265.28 1485.76,1174.73 1291.34,980.32 1049.21,980.32 452.76,383.86 216.54,383.86 38.61,561.78 38.61,2420.5 73.82,2455.71 550.2,2455.71 CS502.1@681.1,2586.61 ; CS502.1@679.72,2586.61 CS502.1@681.1,2586.61
  Bottom Layer w50: S5V-1.2 S5V-1.1@214.57,3257.87
VM: CM1.1 CVM1.1 NTC.2 pad.107@4173.23,1210.63 pad.107@4173.23,1387.8 pad.107@4173.23,2549.21 pad.107@4173.23,2726.38 pad.107@4173.23,3887.8 pad.107@4173.23,4064.96 Q1.D Q3.D Q5.D | length 1220.3
  Top Layer w60: 1555.12,4379.92 NTC.2 1692.88,4507.84 ; 1791.34,3897.64 CM1.1 ; 1929.13,3996.06 CM1.1 ; 2086.61,3897.64 CM1.1
  Bottom Layer w60: 1555.12,4409.45 NTC.2 1653.51,4507.84 ; 1811.02,3897.64 CM1.1 ; 1929.13,4015.75 CM1.1 ; 2057.09,3897.64 CM1.1
  other v1: 4114.17,1269.69 4173.23,1269.69 4232.28,1269.69 4114.17,1328.74 4173.23,1328.74 4232.28,1328.74 4114.17,2608.27 4173.23,2608.27 4232.28,2608.27 4114.17,2667.32 4173.23,2667.32 4232.28,2667.32 4114.17,3946.85 4173.23,3946.85 4232.28,3946.85 4114.17,4005.91 4173.23,4005.91 4232.28,4005.91
VN: ET2251.44 RG4.2 | length 1990.7
  Top Layer w10: ET2251.44 2045.28,1257.87 v1(2102.36,1200.79)
  Top Layer w40: v1(2755.91,1562.99) RG4.2
  Bottom Layer w40: v1(2102.36,1200.79) 2228.35,1074.8 2464.57,1074.8 2755.91,1366.14 v1(2755.91,1562.99)
VP: ET2251.11 RG3.2 | length 1748.8
  Top Layer w10: ET2251.11 2234.25,1604.33 2318.9,1688.98 2433.07,1688.98
  Top Layer w40: 2437.01,1700.79 2437.01,1913.39 RG3.2 RG3.2@3318.9,2799.21
VR1: RVR1.2 VR1.2 VR-1.1 | length 663
  Top Layer w30: VR1.2 940.94,279.53 940.94,551.18 1019.69,629.92 VR-1.1 1177.17,629.92 RVR1.2@1181.1,625.98
VR2: RVR2.2 VR2.2 VR-2.1 | length 669.5
  Top Layer w30: RVR2.2 VR-2.1 1940.94,539.37 1940.94,287.4 VR2.2
WN: ET2251.45 RG6.2 | length 3158.7
  Top Layer w10: ET2251.45 2064.96,1309.06 2098.43,1275.59 v1(2129.92,1275.59)
  Top Layer w40: v1(2748.03,2464.57) 3318.9,3035.43 RG6.2
  Bottom Layer w40: v1(2129.92,1275.59) 2259.84,1145.67 2429.13,1145.67 2661.42,1377.95 2661.42,2377.95 v1(2748.03,2464.57)
WP: ET2251.17 RG5.2 | length 3000.9
  Top Layer w10: ET2251.17 2045.28,1753.94 2125.98,1834.65 2125.98,1956.69 2157.48,1988.19
  Top Layer w40: 2145.67,1972.44 2165.35,1992.13 2385.83,2212.6 2385.83,2413.39 3003.94,3031.5 3003.94,3820.87 RG5.2@3318.9,4135.83
XTALI: 12MHz.2 C5.2 ET2251.32 J2.2 R3.1 | length 1515.8
  Top Layer w10: 12MHz.2 1070.51,1442.56 1749.11,1442.56 1792.77,1486.22 ET2251.32
  Top Layer w30: 12MHz.2@1049.21,1322.83 C5.2 R3.1@1127.95,1192.91
  Bottom Layer w20: J2.2@728.35,1161.42 1059.06,1161.42 v2(1090.55,1192.91)
XTALO: 12MHz.1 C6.2 ET2251.33 J2.1 R3.2 | length 1377.7
  Top Layer w10: 12MHz.1 1426.53,1424.56 1756.56,1424.56 1798.54,1466.54 ET2251.33
  Top Layer w20: J2.1@728.35,1062.99 1153.54,1062.99 1285.43,1194.88 C6.2@1289.37,1198.82
  Top Layer w30: R3.2 C6.2@1281.5,1192.91 ; C6.2@1285.43,1194.88 12MHz.1@1285.43,1326.77
pads on no net: 78D05AL-S. ET2251.1 ET2251.2 ET2251.6 ET2251.7 ET2251.8 ET2251.9 ET2251.13 ET2251.14 ET2251.15 ET2251.19 ET2251.20 ET2251.21 ET2251.22 ET2251.46 ET2251.47 ET2251.48 HOLD1.1 HOLD2.1 HOLD3.1 HOLD4.1 S-POWER.3 VR1.4 VR1.5 VR1.6 VR2.4 VR2.5 VR2.6

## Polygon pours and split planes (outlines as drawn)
VM on Top Layer "Bottom Layer-No Net" (hatched 90Degree grid 8 track 10, pour order 19): 1493.27,4133.86 1830.71,3818.9 2303.15,3818.9 2864.17,3986.22 3198.82,4320.87 3986.22,4320.87 4084.65,4232.28 4084.65,3996.06 4251.97,3996.06 4251.97,4478.35 4084.65,4606.3 3198.82,4606.3 2312.99,4064.96 1899.61,4064.96 1742.13,4606.3 1493.27,4606.3
NetNTC_1 on Top Layer "Bottom Layer-No Net" (hatched 90Degree grid 8 track 10, pour order 20): 492.13,4133.86 1338.58,4133.86 1338.58,4606.3 492.13,4606.3
PGND on Top Layer "Bottom Layer-No Net" (hatched 90Degree grid 8 track 10, pour order 22): 492.13,3533.46 944.88,3533.46 1624.02,3257.87 2814.96,3257.87 2814.96,3592.52 1624.02,3592.52 944.88,3986.22 492.13,3986.22
MW on Top Layer "Bottom Layer-No Net" (hatched 90Degree grid 8 track 10, pour order 27): 3450.68,3818.9 3407.37,3779.53 3405.51,3681.1 3444.88,3651.57 3671.26,3651.57 3779.53,3582.68 3779.53,3405.51 4045.28,3405.51 4311.02,3425.2 3710.63,3818.9
MV on Top Layer "Bottom Layer-No Net" (hatched 90Degree grid 8 track 10, pour order 26): 3450.68,2480.32 3407.37,2440.94 3405.51,2342.52 3444.88,2312.99 3671.26,2312.99 3779.53,2244.09 3779.53,2066.93 4045.28,2066.93 4311.02,2086.61 3710.63,2480.32
MU on Top Layer "Bottom Layer-No Net" (hatched 90Degree grid 8 track 10, pour order 25): 3450.68,1141.73 3407.37,1102.36 3405.51,1003.94 3444.88,974.41 3671.26,974.41 3779.53,905.51 3779.53,728.35 4045.28,728.35 4311.02,748.03 3710.63,1141.73
MV on Top Layer "Bottom Layer-No Net" (hatched 90Degree grid 8 track 10, pour order 28): 3986.22,2253.94 3986.22,1850.39 4360.24,1850.39 4442.91,1935.04 4442.91,2116.14 4291.34,2253.94
MU on Top Layer "Bottom Layer-No Net" (hatched 90Degree grid 8 track 10, pour order 32): 4488.19,1141.73 4488.19,925.2 4025.59,925.2 4399.61,511.81 4488.19,511.81 4960.63,1023.62 4960.63,1141.73
MW on Top Layer "Bottom Layer-No Net" (hatched 90Degree grid 8 track 10, pour order 31): 4488.19,2913.39 4488.19,3188.98 4192.91,3188.98 4035.43,3543.31 4488.19,3543.31 4960.63,3031.5 4960.63,2913.39
PGND on Top Layer "Bottom Layer-No Net" (hatched 90Degree grid 8 track 10, remove dead copper, pour order 24): 0,3385.83 0,0 2677.17,0 2677.17,433.07 2007.87,1102.36 1992.13,1118.11 1976.38,1118.11 1976.38,1149.61 1992.13,1149.61 1992.13,1377.95 1850.39,1377.95 1850.39,1692.91 1968.5,1692.91 1968.5,1811.02 1732.28,2047.24 1732.28,2992.13 944.88,3385.83
VM on Bottom Layer "Bottom Layer-No Net" (hatched 90Degree grid 8 track 10, pour order 17): 1493.27,4133.86 1830.71,3818.9 2303.15,3818.9 2864.17,3986.22 3198.82,4320.87 3986.22,4320.87 4084.65,4232.28 4084.65,3996.06 4251.97,3996.06 4251.97,4478.35 4084.65,4606.3 3198.82,4606.3 2312.99,4064.96 1899.61,4064.96 1742.13,4606.3 1493.27,4606.3
PGND on Bottom Layer "Bottom Layer-No Net" (hatched 90Degree grid 8 track 10, pour order 21): 492.13,3533.46 944.88,3533.46 1624.02,3257.87 2598.43,3257.87 2834.65,3120.08 3129.92,3120.08 3129.92,3346.46 2814.96,3592.52 1624.02,3592.52 944.88,3986.22 492.13,3986.22
MU on Bottom Layer "Bottom Layer-No Net" (hatched 90Degree grid 8 track 10, pour order 30): 4488.19,1141.73 4488.19,511.81 4960.63,1023.62 4960.63,1141.73
MW on Bottom Layer "Bottom Layer-No Net" (hatched 90Degree grid 8 track 10, pour order 29): 4488.19,2913.39 4488.19,3543.31 4960.63,3031.5 4960.63,2913.39
NetNTC_1 on Bottom Layer "Bottom Layer-No Net" (hatched 90Degree grid 8 track 10, pour order 18): 492.13,4133.86 1338.58,4133.86 1338.58,4606.3 492.13,4606.3
PGND on Bottom Layer "Bottom Layer-No Net" (hatched 90Degree grid 8 track 10, remove dead copper, pour order 23): 0,3385.83 0,0 2677.17,0 2677.17,433.07 2007.87,1102.36 2007.87,1377.95 1850.39,1377.95 1850.39,1692.91 1968.5,1692.91 1968.5,1811.02 1732.28,2047.24 1732.28,2992.13 944.88,3385.83

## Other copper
Top Layer:
  region net VM: 3779.53,4104.33 3779.53,3858.27 4251.97,3858.27 4251.97,4104.33
  region net NetQ5_G: 3425.2,4163.39 3425.2,4025.59 3710.63,4025.59 3710.63,4163.39
  region net COM: 3425.2,3149.61 3425.2,2933.07 3720.47,2933.07 3720.47,3149.61
  region net MV: 4962.6,1931.1 4962.6,2116.14 3779.53,2116.14 3779.53,1931.1
  rectangle net MU: 4490.16,1043.31 4962.6,1801.18
  region net COM: 3385.83,466.54 3385.83,68.9 3720.47,68.9 3720.47,466.54
  region net MW: 3710.63,3858.27 3710.63,3897.64 3444.88,3897.64 3444.88,3858.27
  region net COM: 3710.63,3188.98 3710.63,3228.35 3444.88,3228.35 3444.88,3188.98
  region net NetQ6_G: 3425.2,3494.09 3425.2,3356.3 3710.63,3356.3 3710.63,3494.09
  region net MW: 3779.53,3435.04 3779.53,3188.98 4409.45,3188.98 4409.45,3435.04
  region net NetQ4_G: 3425.2,2155.51 3425.2,2017.72 3710.63,2017.72 3710.63,2155.51
  region net COM: 3710.63,1850.39 3710.63,1889.76 3444.88,1889.76 3444.88,1850.39
  region net MV: 3710.63,2519.69 3710.63,2559.06 3444.88,2559.06 3444.88,2519.69
  region net NetQ3_G: 3425.2,2824.8 3425.2,2687.01 3710.63,2687.01 3710.63,2824.8
  region net NetQ2_G: 3425.2,816.93 3425.2,679.13 3710.63,679.13 3710.63,816.93
  region net MU: 3710.63,1181.1 3710.63,1220.47 3444.88,1220.47 3444.88,1181.1
  region net NetQ1_G: 3425.2,1486.22 3425.2,1348.43 3710.63,1348.43 3710.63,1486.22
  region net COM: 3710.63,511.81 3710.63,551.18 3444.88,551.18 3444.88,511.81
  region net COM: 3425.2,1811.02 3425.2,1594.49 3720.47,1594.49 3720.47,1811.02
  region net VM: 3779.53,2765.75 3779.53,2519.69 4251.97,2519.69 4251.97,2765.75
  region net VM: 3779.53,1427.17 3779.53,1181.1 4251.97,1181.1 4251.97,1427.17
  region net MU: 3779.53,757.87 3779.53,511.81 4409.45,511.81 4409.45,757.87
  region net MV: 3828.74,2096.46 3828.74,1850.39 4301.18,1850.39 4301.18,2096.46
  rectangle net MW: 4490.16,2253.94 4962.6,3011.81
  region net PGND: 2834.65,466.54 2834.65,68.9 3188.98,68.9 3188.98,466.54
Bottom Layer:
  region net VM: 4251.97,1141.73 4251.97,4448.82 4084.65,4448.82 4084.65,1141.73
  region net COM: 3720.47,68.9 3720.47,3149.61 3425.2,3149.61 3425.2,68.9
  region net MV: 4962.6,1931.1 4962.6,2116.14 4488.19,2116.14 4488.19,1931.1
  rectangle net MU: 4490.16,1043.31 4962.6,1801.18
  rectangle net MW: 4490.16,2253.94 4962.6,3011.81
  region net COM: 3385.83,462.6 3385.83,68.9 3720.47,68.9 3720.47,462.6
  region net PGND: 3129.92,78.74 3129.92,3159.45 2834.65,3159.45 2834.65,78.74

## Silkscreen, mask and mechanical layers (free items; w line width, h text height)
Top Overlay:
  rectangle: 3582.68,4212.6 4665.35,4704.72
  text "ET2251-DEMO-V1" at 2416.22,4271.83 h60
  text "2015.10.30" at 2402.22,4141.83 h60
  text "SGND" at 9.84,2962.6 h30
  text "S15V" at 19.69,2765.75 h30
  text "S5V" at 19.69,2667.32 h30
  text "W" at 4291.34,2401.57 h120 r270
  text "HU" at 39.37,2116.14 h30
  text "HV" at 39.37,2017.72 h30
  text "HW" at 39.37,1919.29 h30
  text "SGND" at 9.84,1820.87 h30
  text "U" at 4291.34,1732.28 h120 r270
  text "S5V" at 9.84,1722.44 h30
  text "SGND" at 551.18,1444.88 h30
  text "SGND" at 9.84,1387.8 h30
  text "RX" at 590.55,1346.46 h30
  text "TX" at 29.53,1289.37 h30
  text "TX" at 590.55,1248.03 h30
  text "RX" at 29.53,1190.94 h30
  text "XI" at 590.55,1149.61 h30
  text "S5V" at 19.69,1092.52 h30
  text "XO" at 590.55,1041.34 h30
  text "SGND" at 1407.48,816.93 h30 r270
  text "CH0" at 1505.91,807.09 h30 r270
  text "CH2" at 1604.33,807.09 h30 r270
  text "CH4" at 1702.76,807.09 h30 r270
  text "CH6" at 1801.18,807.09 h30 r270
  text "SGND" at 9.84,757.87 h30
  text "SDA" at 29.53,659.45 h30
  text "SCL" at 29.53,561.02 h30
  text "S5V" at 11.81,468.5 h30
Mechanical 1:
  lines w10: 0,0 5039.37,0 5039.37,4724.41 0,4724.41 0,0
  lines w15.75: 1988.19,1740.16 1988.19,1972.44 ; 2173.23,1669.29 2271.65,1814.96 ; 2204.72,1326.77 2314.96,1236.22 ; 2240.16,1535.43 2409.45,1535.43
  lines w50: 490.16,4061.02 982.28,4061.02 ; 4480.32,1866.14 4960.63,1866.14 ; 4480.32,2185.04 4960.63,2185.04
Mechanical 2:
  circle w3.94: c1998.03,1917.32 r49.21
  circle w3.94: c1988.19,1980.32 r49.21
  circle w3.94: c2000,1842.52 r49.21
  circle w3.94: c2007.87,1767.72 r49.21
  circle w3.94: c2222.44,2279.53 r49.21
  circle w3.94: c2435.04,1940.94 r49.21
  circle w3.94: c2797.24,2409.45 r49.21
  circle w3.94: c3250,2866.14 r49.21
  circle w3.94: c2228.35,1724.41 r49.21
  circle w3.94: c2267.72,1527.56 r49.21
  circle w3.94: c2435.04,1783.46 r49.21
  circle w3.94: c2438.98,1555.12 r49.21
  circle w3.94: c2360.24,1551.18 r49.21
  circle w3.94: c2222.44,1311.02 r49.21
  circle w3.94: c2690.94,2507.87 r49.21
  circle w3.94: c2584.65,2043.31 r49.21
  circle w3.94: c3230.32,3460.63 r49.21
  circle w3.94: c3131.89,2948.82 r49.21
  circle w3.94: c3250,3543.31 r49.21
  circle w3.94: c2513.78,2090.55 r49.21
  circle w3.94: c2753.94,1452.76 r49.21
  circle w3.94: c2287.4,1862.2 r49.21
Drill Drawing:
  text ".Legend" at 5196.85,19.68 h60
